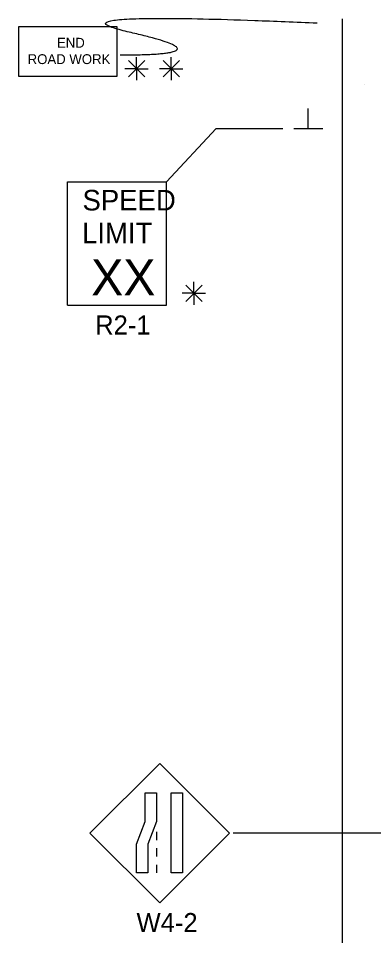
# Model space of a CAD drawing. Extents: x 16590 to 19508, y 5703 to 6974.
# Drawn here: x 17775 to 17913.2, y 6568 to 6925.5 of the extents above; entities that cross this region are included whole.
import ezdxf

# ---------------------------------------------------------------- set-up
doc = ezdxf.new("R2010")
doc.units = 0
for name, color, linetype in [('BORDER', 7, 'Continuous'), ('PAVT_EDGE_EX', 7, 'Continuous'), ('TRAFFIC_SIGNS_PR', 7, 'Continuous'), ('TYPICAL_TEXT_DIMEN_PR', 7, 'Continuous')]:
    doc.layers.add(name, color=color, linetype=linetype)

msp = doc.modelspace()

# ---------------------------------------------------------------- linework, layer by layer
at = {"layer": 'BORDER'}
msp.add_line((17909.54, 6899.78), (17909.54, 6899.78), dxfattribs=at)
at = {"layer": 'PAVT_EDGE_EX'}
msp.add_line((17900.96, 6925.33), (17900.96, 6268.58), dxfattribs=at)
at = {"layer": 'TRAFFIC_SIGNS_PR'}
for p, q in [((17794.15, 6861.76), (17832.6, 6861.76)), ((17794.15, 6813.7), (17794.15, 6861.76)), ((17832.6, 6813.7), (17832.6, 6861.76)), ((17794.15, 6813.7), (17832.6, 6813.7)), ((17830, 6635.07), (17802.85, 6607.92)), ((17857.15, 6607.92), (17830, 6635.07)), ((17802.85, 6607.92), (17830, 6580.77)), ((17828.75, 6608.41), (17828.75, 6605.21)), ((17830, 6580.77), (17857.15, 6607.92)), ((17828.75, 6602.01), (17828.75, 6598.81)), ((17828.75, 6595.61), (17828.75, 6592.41))]:
    msp.add_line(p, q, dxfattribs=at)
for points in [[(17774.97, 6902.91), (17813.42, 6902.91), (17813.42, 6922.13), (17774.97, 6922.13)], [(17828.75, 6623.66), (17828.75, 6612.48), (17825.41, 6603.59), (17825.41, 6592.41), (17820.92, 6592.41), (17820.92, 6603.59), (17824.26, 6612.48), (17824.26, 6623.66)], [(17838.89, 6623.66), (17838.89, 6592.41), (17834.4, 6592.41), (17834.4, 6623.66)]]:
    msp.add_lwpolyline(points, close=True, dxfattribs=at)
msp.add_open_spline([(17814.53, 6911.21), (17857.04, 6911.21), (17780.52, 6928.63), (17891.31, 6923.69)], degree=2, dxfattribs=at)
at = {"layer": 'TYPICAL_TEXT_DIMEN_PR'}
for p, q in [((17817.78, 6909.04), (17824.15, 6902.66)), ((17824.15, 6909.04), (17817.78, 6902.66)), ((17820.96, 6905.85), (17820.96, 6910.31)), ((17831.28, 6909.04), (17837.66, 6902.66)), ((17837.66, 6909.04), (17831.28, 6902.66)), ((17834.47, 6905.85), (17834.47, 6910.31)), ((17820.96, 6905.85), (17816.43, 6905.85)), ((17820.96, 6905.85), (17824.15, 6905.85)), ((17820.96, 6905.85), (17825.44, 6905.85)), ((17820.96, 6905.85), (17820.96, 6901.35)), ((17834.47, 6905.85), (17829.94, 6905.85)), ((17834.47, 6905.85), (17837.66, 6905.85)), ((17834.47, 6905.85), (17838.95, 6905.85)), ((17834.47, 6905.85), (17834.47, 6901.35)), ((17887.83, 6882.5), (17887.83, 6890.28)), ((17832.6, 6861.76), (17851.96, 6882.5)), ((17851.96, 6882.5), (17877.96, 6882.5)), ((17882.21, 6882.5), (17893.46, 6882.5)), ((17840.12, 6821.53), (17846.5, 6815.16)), ((17846.5, 6821.53), (17840.12, 6815.16)), ((17843.31, 6818.34), (17843.31, 6822.8)), ((17843.31, 6818.34), (17838.78, 6818.34)), ((17843.31, 6818.34), (17846.5, 6818.34)), ((17843.31, 6818.34), (17847.79, 6818.34)), ((17843.31, 6818.34), (17843.31, 6813.84)), ((17858.57, 6607.97), (17921.15, 6607.97))]:
    msp.add_line(p, q, dxfattribs=at)

# ---------------------------------------------------------------- texts
at = {"layer": 'TRAFFIC_SIGNS_PR'}
for s, height, p in [('END', 3.836, (17789.99, 6914.05)), ('ROAD WORK', 3.836, (17778.58, 6907.66)), ('SPEED', 8.01, (17799.93, 6850.61)), ('LIMIT', 8.01, (17799.76, 6837.79)), ('XX', 14.048, (17803.28, 6817.46)), ('R2-1', 7.449, (17804.84, 6802.24)), ('W4-2', 7.44, (17820.96, 6569.33))]:
    msp.add_text(s, height=height, dxfattribs=at).set_placement(p)

doc.saveas('drawing.dxf')
